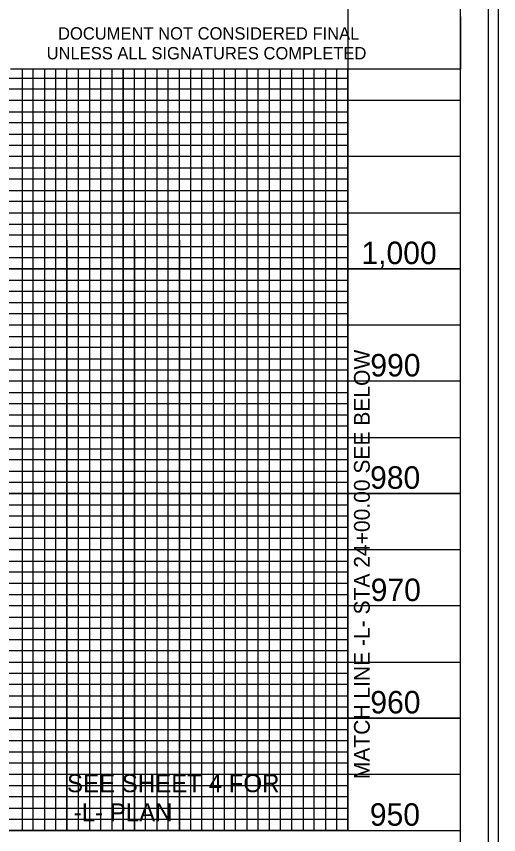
# Model space of a CAD drawing. Extents: x 1623313 to 1628771, y 891211 to 901910.
# Drawn here: x 1624782.4 to 1624996.9, y 901332.6 to 901696.9 of the extents above; entities that cross this region are included whole.
import ezdxf

# ---------------------------------------------------------------- set-up
doc = ezdxf.new("R2010")
doc.units = 0
for name, color, linetype in [('Default', 7, 'Continuous'), ('Matchline', 7, 'Continuous'), ('Matchline Text', 7, 'Continuous'), ('Prop DSN Text', 7, 'Continuous'), ('Prop PHM Black Shape', 7, 'Continuous'), ('Scratch_Level_0', 7, 'Continuous'), ('Sheet DOT Grid CELL', 7, 'Continuous'), ('Sheet Layout Profile Border Port 1', 7, 'Continuous'), ('Sheet Plot Border Inside CELL', 7, 'Continuous'), ('Sheet Plot Border Outside CELL', 7, 'Continuous'), ('Sheet Profile CELL', 7, 'Continuous'), ('Sheet Profile Grid Major CELL', 7, 'Continuous'), ('Sheet Profile Grid Middle CELL', 7, 'Continuous'), ('Sheet Profile Grid Minor CELL', 7, 'Continuous'), ('Sheet Sticker Exception Certification CELL', 7, 'Continuous')]:
    doc.layers.add(name, color=color, linetype=linetype)

msp = doc.modelspace()

# ---------------------------------------------------------------- linework, layer by layer
at = {"layer": 'Matchline'}
msp.add_line((1624929.95, 901673.49), (1624929.95, 901334.54), dxfattribs=at)
at = {"layer": 'Prop DSN Text'}
msp.add_lwpolyline([(1624929.95, 901334.54), (1624804.95, 901334.54), (1624804.95, 901359.54), (1624929.95, 901359.54)], close=True, dxfattribs=at)
at = {"layer": 'Prop PHM Black Shape'}
msp.add_lwpolyline([(1624804.95, 901359.54), (1624929.95, 901359.54), (1624929.95, 901334.45), (1624804.95, 901334.45)], close=True, dxfattribs=at)
at = {"layer": 'Scratch_Level_0'}
msp.add_lwpolyline([(1623529.95, 901824.45), (1624929.95, 901824.45), (1624929.95, 901334.45), (1623529.95, 901334.45)], close=True, dxfattribs=at)
at = {"layer": 'Sheet DOT Grid CELL'}
for p, q in [((1624829.95, 901334.45), (1624829.95, 901673.4)), ((1624879.95, 901334.45), (1624879.95, 901673.4)), ((1624929.95, 901334.45), (1624929.95, 901673.4)), ((1624979.95, 901634.45), (1623479.95, 901634.45)), ((1624979.95, 901584.45), (1623479.95, 901584.45)), ((1624979.95, 901534.45), (1623479.95, 901534.45)), ((1624979.95, 901484.45), (1623479.95, 901484.45)), ((1624979.95, 901434.45), (1623479.95, 901434.45)), ((1624979.95, 901384.45), (1623479.95, 901384.45))]:
    msp.add_line(p, q, dxfattribs=at)
at = {"layer": 'Sheet Layout Profile Border Port 1'}
msp.add_lwpolyline([(1623529.95, 901673.4), (1623529.95, 901334.45), (1624929.95, 901334.45), (1624929.95, 901673.4)], dxfattribs=at)
at = {"layer": 'Sheet Plot Border Inside CELL'}
msp.add_lwpolyline([(1623325.95, 900781.9), (1624992.45, 900781.9), (1624992.45, 901837), (1623325.95, 901837)], close=True, dxfattribs=at)
at = {"layer": 'Sheet Plot Border Outside CELL'}
msp.add_lwpolyline([(1623312.95, 900759.45), (1624996.95, 900759.45), (1624996.95, 901859.45), (1623312.95, 901859.45)], close=True, dxfattribs=at)
at = {"layer": 'Sheet Profile CELL'}
msp.add_line((1623479.95, 901334.45), (1624979.95, 901334.45), dxfattribs=at)
msp.add_lwpolyline([(1624979.95, 901834.45), (1623479.95, 901834.45), (1623479.95, 900784.45), (1624979.95, 900784.45)], close=True, dxfattribs=at)
at = {"layer": 'Sheet Profile Grid Major CELL'}
for points in [[(1624929.95, 901673.4), (1624929.95, 901334.45), (1624979.95, 901334.45), (1624979.95, 901684.45)], [(1624829.95, 901673.4), (1624829.95, 901334.45), (1624879.95, 901334.45), (1624879.95, 901334.45), (1624879.95, 901673.4)], [(1624979.95, 901634.45), (1623479.95, 901634.45), (1623479.95, 901584.45), (1624979.95, 901584.45)], [(1624979.95, 901534.45), (1623479.95, 901534.45), (1623479.95, 901484.45), (1624979.95, 901484.45)], [(1624979.95, 901434.45), (1623479.95, 901434.45), (1623479.95, 901434.45), (1623479.95, 901384.45), (1624979.95, 901384.45)]]:
    msp.add_lwpolyline(points, dxfattribs=at)
at = {"layer": 'Sheet Profile Grid Middle CELL'}
for points in [[(1624754.95, 901334.45), (1624804.95, 901334.45), (1624804.95, 901673.4)], [(1624804.95, 901597.25), (1624804.95, 901334.45), (1624854.95, 901334.45), (1624854.95, 901673.4)], [(1624854.95, 901597.25), (1624854.95, 901334.45), (1624904.95, 901334.45), (1624904.95, 901673.4)], [(1624979.95, 901659.45), (1623479.95, 901659.45), (1623479.95, 901609.45), (1624804.95, 901609.45)], [(1624804.95, 901609.45), (1624979.95, 901609.45)], [(1624979.95, 901559.45), (1623479.95, 901559.45), (1623479.95, 901509.45), (1624979.95, 901509.45)], [(1624979.95, 901459.45), (1623479.95, 901459.45), (1623479.95, 901409.45), (1624979.95, 901409.45)], [(1624979.95, 901359.45), (1623479.95, 901359.45)]]:
    msp.add_lwpolyline(points, dxfattribs=at)
at = {"layer": 'Sheet Profile Grid Minor CELL'}
for p, q in [((1623529.95, 901669.45), (1624929.95, 901669.45)), ((1624929.95, 901649.45), (1623529.95, 901649.45)), ((1623529.95, 901644.45), (1624929.95, 901644.45)), ((1624929.95, 901624.45), (1623529.95, 901624.45)), ((1623529.95, 901619.45), (1624929.95, 901619.45)), ((1624929.95, 901599.45), (1623529.95, 901599.45)), ((1623529.95, 901594.45), (1624929.95, 901594.45)), ((1624929.95, 901589.45), (1623529.95, 901589.45)), ((1623529.95, 901579.45), (1624929.95, 901579.45)), ((1624929.95, 901574.45), (1623529.95, 901574.45)), ((1623529.95, 901569.45), (1624929.95, 901569.45)), ((1624929.95, 901564.45), (1623529.95, 901564.45)), ((1623529.95, 901554.45), (1624929.95, 901554.45)), ((1624929.95, 901549.45), (1623529.95, 901549.45)), ((1623529.95, 901544.45), (1624929.95, 901544.45)), ((1624929.95, 901539.45), (1623529.95, 901539.45)), ((1623529.95, 901529.45), (1624929.95, 901529.45)), ((1624929.95, 901524.45), (1623529.95, 901524.45)), ((1623529.95, 901519.45), (1624929.95, 901519.45)), ((1624929.95, 901514.45), (1623529.95, 901514.45)), ((1623529.95, 901504.45), (1624929.95, 901504.45)), ((1624929.95, 901499.45), (1623529.95, 901499.45)), ((1623529.95, 901494.45), (1624929.95, 901494.45)), ((1624929.95, 901489.45), (1623529.95, 901489.45)), ((1623529.95, 901479.45), (1624929.95, 901479.45)), ((1624929.95, 901474.45), (1623529.95, 901474.45)), ((1623529.95, 901469.45), (1624929.95, 901469.45)), ((1624929.95, 901464.45), (1623529.95, 901464.45)), ((1623529.95, 901454.45), (1624929.95, 901454.45)), ((1624929.95, 901449.45), (1623529.95, 901449.45)), ((1624929.95, 901444.45), (1623529.95, 901444.45)), ((1624929.95, 901439.45), (1623529.95, 901439.45)), ((1623529.95, 901429.45), (1624929.95, 901429.45)), ((1624929.95, 901424.45), (1623529.95, 901424.45)), ((1623529.95, 901419.45), (1624929.95, 901419.45)), ((1624929.95, 901414.45), (1623529.95, 901414.45)), ((1623529.95, 901404.45), (1624929.95, 901404.45)), ((1624929.95, 901399.45), (1623529.95, 901399.45)), ((1623529.95, 901394.45), (1624929.95, 901394.45)), ((1624929.95, 901389.45), (1623529.95, 901389.45)), ((1623529.95, 901379.45), (1624929.95, 901379.45)), ((1624929.95, 901374.45), (1623529.95, 901374.45)), ((1623529.95, 901369.45), (1624929.95, 901369.45)), ((1624929.95, 901364.45), (1623529.95, 901364.45)), ((1623529.95, 901354.45), (1624929.95, 901354.45)), ((1624929.95, 901349.45), (1623529.95, 901349.45)), ((1623529.95, 901344.45), (1624929.95, 901344.45))]:
    msp.add_line(p, q, dxfattribs=at)
for points in [[(1624784.95, 901673.4), (1624784.95, 901334.45), (1624789.95, 901334.45), (1624789.95, 901673.4)], [(1624794.95, 901673.4), (1624794.95, 901334.45), (1624799.95, 901334.45), (1624799.95, 901673.4)], [(1624809.95, 901673.4), (1624809.95, 901334.45), (1624809.95, 901334.45), (1624814.95, 901334.45), (1624819.95, 901334.45), (1624819.95, 901673.4)], [(1624814.95, 901673.4), (1624814.95, 901334.45)], [(1624824.94, 901673.4), (1624824.85, 901334.5), (1624829.85, 901334.5), (1624834.95, 901334.45), (1624834.95, 901673.4)], [(1624834.95, 901597.25), (1624834.95, 901334.45), (1624839.95, 901334.45), (1624839.95, 901673.4)], [(1624844.95, 901673.4), (1624844.95, 901334.45), (1624849.95, 901334.45), (1624849.95, 901673.4)], [(1624859.95, 901673.4), (1624859.95, 901334.45), (1624864.95, 901334.45), (1624864.95, 901673.4)], [(1624869.95, 901673.4), (1624869.95, 901334.45), (1624874.95, 901334.45), (1624874.95, 901673.4)], [(1624884.95, 901673.4), (1624884.95, 901334.45), (1624889.95, 901334.45), (1624889.95, 901673.4)], [(1624894.95, 901673.4), (1624894.95, 901334.45), (1624899.95, 901334.45), (1624899.95, 901673.4)], [(1624909.95, 901673.4), (1624909.95, 901334.45), (1624914.95, 901334.45), (1624914.95, 901673.4)], [(1624919.95, 901673.4), (1624919.95, 901334.45), (1624924.95, 901334.45), (1624924.95, 901673.4)], [(1624929.95, 901664.45), (1623529.95, 901664.45), (1623529.95, 901654.45), (1624929.95, 901654.45)], [(1624929.95, 901639.45), (1623529.95, 901639.45), (1623529.95, 901629.45), (1624929.95, 901629.45)], [(1624929.95, 901614.45), (1623529.95, 901614.45), (1623529.95, 901604.45), (1624929.95, 901604.45)], [(1624929.95, 901339.45), (1623529.95, 901339.45)]]:
    msp.add_lwpolyline(points, dxfattribs=at)
at = {"layer": 'Sheet Sticker Exception Certification CELL'}
for p, q in [((1624979.93, 901696.89), (1624979.93, 901673.39)), ((1624979.93, 901696.89), (1624979.93, 901673.39)), ((1624979.93, 901673.4), (1624779.9, 901673.4)), ((1624979.93, 901673.4), (1624779.9, 901673.4))]:
    msp.add_line(p, q, dxfattribs=at)

# ---------------------------------------------------------------- texts
at = {"layer": 'Default'}
for s, p in [('1,000', (1624935.93, 901586.61)), ('990', (1624939.89, 901536.61)), ('980', (1624939.78, 901486.61)), ('970', (1624940.05, 901436.61)), ('960', (1624939.89, 901386.61)), ('950', (1624939.67, 901336.61))]:
    msp.add_text(s, height=10, dxfattribs=at).set_placement(p)
at = {"layer": 'Matchline Text'}
msp.add_text('MATCH LINE -L- STA 24+00.00 SEE BELOW', height=7, rotation=90, dxfattribs=at).set_placement((1624939.62, 901357.32))
at = {"layer": 'Prop DSN Text'}
for s, p in [('SEE SHEET 4 FOR', (1624804.95, 901351.54)), (' -L- PLAN', (1624804.95, 901338.54))]:
    msp.add_text(s, height=8, dxfattribs=at).set_placement(p)
at = {"layer": 'Sheet Sticker Exception Certification CELL'}
for s, p in [('DOCUMENT NOT CONSIDERED FINAL', (1624800.97, 901686.55)), ('DOCUMENT NOT CONSIDERED FINAL', (1624800.97, 901686.55)), ('UNLESS ALL SIGNATURES COMPLETED', (1624795.9, 901677.75)), ('UNLESS ALL SIGNATURES COMPLETED', (1624795.9, 901677.75))]:
    msp.add_text(s, height=5.5, dxfattribs=at).set_placement(p)

doc.saveas('drawing.dxf')
